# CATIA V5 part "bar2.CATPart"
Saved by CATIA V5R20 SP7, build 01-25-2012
Part number: bar2
Bounding box of the stored display mesh (mm): x 226 to 406, y -12 to 12, z -10 to 10
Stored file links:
  D:\thinkmotion-MPB\Dropbox\Pack 1 sylvain\CFAO_2010_yyang\yyang\CFAO_2010_yyang\bar2.CATPart
  D:\thinkmotion-MPB\Dropbox\Pack 1 sylvain\CFAO_2010_yyang\yyang\CFAO_2010_yyang\yyang.CATProduct
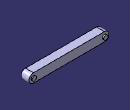
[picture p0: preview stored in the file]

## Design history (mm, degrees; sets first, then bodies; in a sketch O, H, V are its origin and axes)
External parameters (linked from other documents)
  `External.demi_largeur du bar` = 10 mm
  `External.rayon du trou des liaisons` = 5 mm
  `External.demi-distance entre les des pivot` = 9 mm
  External.epaisseur = 3 mm
  `External.epaisseur du pivot` = 2 mm
Set1
  Plane1: linked copy from another document
  Point1: linked copy from another document
  Point2: linked copy from another document
  Line1: linked copy from another document
Body1 (main body)
  Sketch1 on Plane1, origin (0, 0, 0), H (-1, 0, 0), V (0, 0, 1)
    construction line L1 (-396, 0) -> (-236, 0)
    point P1 (-396, 0)
    point P2 (-236, 0)
    line L2 (-396, 10) -> (-236, 10)
    line L3 (-236, -10) -> (-396, -10)
    arc A1 centre (-236, 0) radius 10 from (-236, 10) to (-236, -10) cw
    arc A2 centre (-396, 0) radius 10 from (-396, -10) to (-396, 10) cw
    reference projected point E1 (-396, 0) from Point1
    reference projected point E2 (-236, 0) from Point2
    reference projected line E3 (-236, 0) -> (-416, 0) from Line1
    distance L2 E3 = 10 {= `External.demi_largeur du bar`}
    horizontal: L1 H
    tangency: A1 L2, A2 L2, A1 L3, A2 L3
    coincidence: P1 E1, P2 E2
  Pad1: profile Sketch1, direction (0, 1, 0), length 9 {= `External.demi-distance entre les des pivot`}, mirrored extent
  Sketch2 on start face of Pad1, origin (0, -9, 0), H (1, 0, 0), V (0, 0, 1)
    circle A1 centre (236, 0) radius 5
    point P1 (236, 0)
    reference projected point E1 (236, 0) from Point2
    reference projected point E2 (236, 0) from Point2
    distance A1 E2 = 5 {= `External.rayon du trou des liaisons`}
    coincidence: P1 E1
  Pad2: profile Sketch2, direction (0, -1, 0), length 3 {= External.epaisseur}
  Sketch3 on start face of Pad1, origin (0, -9, 0), H (1, 0, 0), V (0, 0, 1)
    circle A1 centre (396, 0) radius 5
    point P1 (396, 0)
    reference projected point E1 (396, 0) from Point1
    reference projected point E2 (396, 0) from Point1
    distance A1 E2 = 5 {= `External.rayon du trou des liaisons`}
    coincidence: P1 E1
  Pad3: profile Sketch3, direction (0, -1, 0), length 2 {= `External.epaisseur du pivot`}
  Mirror1: of Pad2, Pad3, about Plane1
